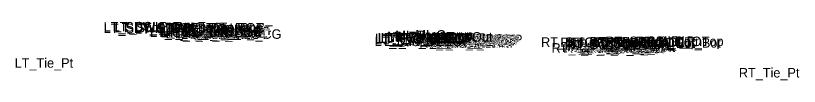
# Model space of a CAD drawing. Extents: x 0 to 4229, y -1 to 9523.
# Drawn here: x 1064.7 to 1230.2, y 5005.6 to 5017.9 of the extents above; entities that cross this region are included whole.
import ezdxf

# ---------------------------------------------------------------- set-up
doc = ezdxf.new("R2010")
doc.units = 0
doc.layers.add('Default', color=7, linetype='Continuous')

msp = doc.modelspace()

# ---------------------------------------------------------------- texts
at = {"layer": 'Default'}
for s, p in [('LT_SDWK_Out_Top', (1083.24, 5015.87)), ('LT_SDWK_Out_Bot', (1083.27, 5015.54)), ('LT_CSLP_Pnt', (1085.17, 5015.9)), ('LT_Sub_Trench_Out_DLT', (1085.58, 5015.7)), ('LT_SDWK_In_Top', (1089.86, 5015.77)), ('LT_SDWK_In_Bot', (1089.89, 5015.44)), ('LT_CG_Top_Face', (1094.76, 5015.66)), ('LT_CG_Top_BOC', (1095.28, 5015.66)), ('LT_CG1_Shelf_Out', (1093.05, 5014.69)), ('LT_CG_Bot_BOC', (1095.31, 5014.68)), ('LT_CG_Top_Gut', (1095.74, 5015.16)), ('LT_Sub_OEOP', (1096.37, 5014.45)), ('LT_Sub_OEOT_CG', (1096.87, 5014.34)), ('LT_CG_Bot_IE', (1099.41, 5014.59)), ('LT_Sub_OEOT', (1099.58, 5014.29)), ('LT_PV2_OEOT', (1099.67, 5014.92)), ('LT_PV3_OEOT', (1099.67, 5014.67)), ('LT_PV1_OEOT', (1100.24, 5015.17)), ('LT_PV1_PGL', (1143.03, 5013.67)), ('MI_Face In', (1143.15, 5013.83)), ('MI_Top In', (1144.86, 5014.08)), ('MI_Crown', (1149.07, 5014.16)), ('MI_Top Out', (1151.22, 5013.74)), ('LT_Sub_OEEOP', (1140.46, 5012.79)), ('LT_PV2_OEEOP', (1140.56, 5013.42)), ('LT_PV3_OEEOP', (1140.56, 5013.17)), ('LT_PV1_OEEOP', (1141.12, 5013.54)), ('LT_PV2_IEEOP', (1141.2, 5013.42)), ('LT_PV1_IEEOP', (1141.77, 5013.54)), ('LT_PV2_PGL1', (1142.13, 5013.42)), ('LT_PV3_PGL1', (1142.13, 5013.17)), ('LT_PV2_PGL', (1142.46, 5013.42)), ('LT_PV4_PGL', (1142.46, 5012.79)), ('MI_Bot In', (1144.13, 5013.67)), ('RT_Sub_OEEOP', (1149.92, 5012.45)), ('RT_PV2_OEEOP', (1150.01, 5013.07)), ('RT_PV3_OEEOP', (1150.01, 5012.82)), ('RT_PV1_OEEOP', (1150.58, 5013.2)), ('RT_PV2_IEEOP', (1150.66, 5013.07)), ('MI_Face Out', (1151.01, 5013.49)), ('RT_PV1_IEEOP', (1151.22, 5013.2)), ('RT_PV2_PGL1', (1151.58, 5013.07)), ('RT_PV3_PGL1', (1151.58, 5012.82)), ('RT_PV2_PGL', (1151.92, 5013.07)), ('RT_PV4_PGL', (1151.92, 5012.45)), ('MI_Bot Out', (1152.01, 5013.32)), ('RT_PV1_PGL', (1152.48, 5013.32)), ('RT_Sub_Trench_Out_DLT', (1175.62, 5012.64)), ('RT_CG_Top_Face', (1179.71, 5012.6)), ('RT_CG_Top_Gut', (1180.69, 5012.1)), ('RT_PV1_OEOT', (1181.19, 5012.25)), ('RT_CG_Top_BOC', (1181.24, 5012.6)), ('RT_SDWK_In_Top', (1185.81, 5012.71)), ('RT_SDWK_In_Bot', (1185.84, 5012.38)), ('RT_SDWK_Out_Top', (1189.19, 5012.81)), ('RT_SDWK_Out_Bot', (1189.22, 5012.48)), ('RT_Shld_O', (1195.54, 5012.8)), ('CSLP_Pnt', (1197.87, 5012.84)), ('RT_Sub_OEOT_CG', (1177.82, 5011.42)), ('RT_CG1_Shelf_Out', (1180, 5011.56)), ('RT_CG_Bot_IE', (1180.37, 5011.67)), ('RT_Sub_OEOT', (1180.53, 5011.38)), ('RT_PV2_OEOT', (1180.63, 5012)), ('RT_PV3_OEOT', (1180.63, 5011.75)), ('RT_CG_Bot_BOC', (1181.27, 5011.58)), ('RT_Sub_OEOP', (1183.82, 5011.3)), ('LT_Tie_Pt', (1064.46, 5008.24)), ('RT_Tie_Pt', (1217.39, 5006.18))]:
    msp.add_text(s, height=2, dxfattribs=at).set_placement(p)

doc.saveas('drawing.dxf')
